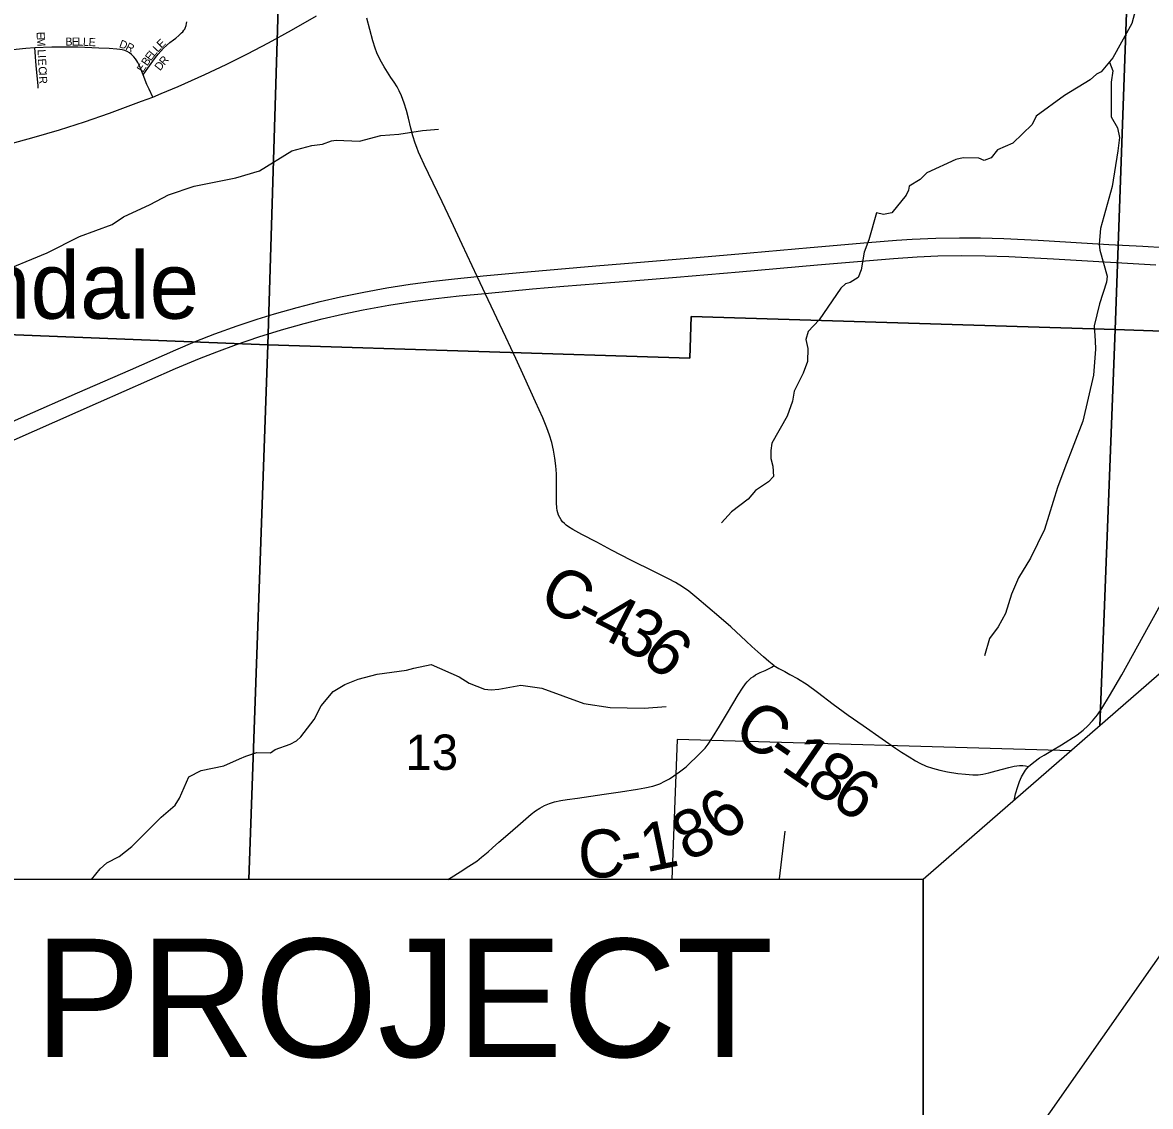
# Model space of a CAD drawing. Extents: x 0 to 34, y 0 to 22.
# Drawn here: x 25.311 to 26.645, y 15.353 to 16.636 of the extents above; entities that cross this region are included whole.
import ezdxf

# ---------------------------------------------------------------- set-up
doc = ezdxf.new("R2010")
doc.units = 0
for name, color, linetype in [('GM_X_County_Road', 7, 'Continuous'), ('GM_X_County_Road_Text', 7, 'Continuous'), ('GM_X_Interstate_Route', 7, 'Continuous'), ('GM_X_Minor_River', 7, 'Continuous'), ('GM_X_Section', 7, 'Continuous'), ('GM_X_Section_Text', 7, 'Continuous'), ('GM_X_Township_Subdivision', 7, 'Continuous'), ('GM_X_Township_Subdivision_Text', 7, 'Continuous'), ('GM_X_Unincorporated_Text', 7, 'Continuous'), ('GM_X_US_Route', 7, 'Continuous'), ('SH_Text', 7, 'Continuous')]:
    doc.layers.add(name, color=color, linetype=linetype)

msp = doc.modelspace()

# ---------------------------------------------------------------- linework, layer by layer
at = {"layer": 'GM_X_County_Road'}
for points in [[(25.7815, 16.4769), (25.7793, 16.4821), (25.7772, 16.4876), (25.7753, 16.4927), (25.7726, 16.5015), (25.7703, 16.5104), (25.7675, 16.5224), (25.7652, 16.5314), (25.7625, 16.5403), (25.7592, 16.549), (25.7566, 16.5547), (25.7539, 16.5595), (25.7504, 16.5648), (25.7467, 16.5704), (25.7385, 16.5833), (25.734, 16.5913), (25.7301, 16.5996), (25.728, 16.6053), (25.7253, 16.614), (25.7183, 16.6408)], [(26.1996, 15.8745), (26.1937, 15.8792), (26.1876, 15.8847), (26.1807, 15.8908), (26.1737, 15.897), (26.1669, 15.9033), (26.1487, 15.9201), (26.1347, 15.9325), (26.1087, 15.9546), (26.099, 15.9624), (26.0917, 15.9677), (26.0833, 15.9727), (26.0751, 15.9772), (26.0584, 15.9855), (26.0305, 15.9992), (26.0078, 16.0109), (25.9902, 16.0203), (25.9727, 16.0295), (25.9618, 16.0354), (25.9566, 16.0387), (25.9542, 16.0405), (25.9519, 16.0425), (25.9498, 16.0447), (25.948, 16.047), (25.9464, 16.0496), (25.9451, 16.0523), (25.9441, 16.0551), (25.9434, 16.0581), (25.9429, 16.0611), (25.9425, 16.0672), (25.9427, 16.0858), (25.9424, 16.1014), (25.9417, 16.1107), (25.9407, 16.12), (25.9391, 16.1292), (25.937, 16.1383), (25.9342, 16.1473), (25.9311, 16.156), (25.9263, 16.1675), (25.9177, 16.1864), (25.9046, 16.2153), (25.8945, 16.238), (25.8826, 16.2632), (25.8581, 16.3149), (25.8494, 16.3334), (25.8487, 16.3349), (25.8309, 16.3728), (25.8178, 16.4009), (25.8072, 16.4233), (25.7911, 16.4568), (25.7858, 16.4677), (25.7815, 16.4769)], [(26.5012, 15.7548), (26.5075, 15.7601), (26.5143, 15.765), (26.5196, 15.7685), (26.5293, 15.7744), (26.54, 15.7805), (26.5585, 15.7924), (26.5658, 15.798), (26.5713, 15.8031), (26.5767, 15.8088), (26.5826, 15.816), (26.588, 15.8235), (26.5969, 15.8385), (26.6116, 15.8635), (26.643, 15.9206), (26.6613, 15.9533)], [(25.8141, 15.621), (25.818, 15.6236), (25.8285, 15.6302), (25.839, 15.6369), (25.8482, 15.643), (25.854, 15.6477), (25.8617, 15.6538), (25.8669, 15.6586), (25.8744, 15.6654), (25.8851, 15.6746), (25.8967, 15.6848), (25.9126, 15.6985), (25.9176, 15.7023), (25.9229, 15.7057), (25.9284, 15.7087), (25.9342, 15.7112), (25.9401, 15.7132), (25.9476, 15.7147), (25.9552, 15.7158), (25.9673, 15.7174), (25.9988, 15.7223), (26.0185, 15.7249), (26.0385, 15.7279), (26.0471, 15.7295), (26.0565, 15.7317), (26.0649, 15.7346), (26.0709, 15.7376), (26.0763, 15.7405), (26.0815, 15.7439), (26.0883, 15.7487), (26.0961, 15.7546), (26.1012, 15.7595), (26.1076, 15.7657), (26.1142, 15.7721), (26.1184, 15.7767), (26.1222, 15.7815), (26.1273, 15.7892), (26.1353, 15.8025), (26.1448, 15.8185), (26.1576, 15.8399), (26.1626, 15.8478), (26.1663, 15.8529), (26.1683, 15.8553), (26.1705, 15.8575), (26.1729, 15.8597), (26.1755, 15.8616), (26.1781, 15.8633), (26.1837, 15.8662), (26.1894, 15.8687), (26.1943, 15.871), (26.1974, 15.8725), (26.1996, 15.8745)], [(26.1996, 15.8745), (26.2055, 15.8708), (26.2127, 15.8672), (26.2188, 15.8639), (26.2276, 15.8591), (26.2391, 15.8518), (26.2515, 15.8428), (26.2701, 15.8286), (26.2877, 15.8158), (26.3055, 15.8033), (26.328, 15.7877), (26.3438, 15.7767), (26.3509, 15.7719), (26.3597, 15.7662), (26.3673, 15.7615), (26.3727, 15.7587), (26.3802, 15.7552), (26.3874, 15.753), (26.396, 15.7507), (26.4051, 15.7487), (26.4173, 15.7467), (26.4266, 15.7457), (26.4354, 15.7451), (26.4415, 15.7452), (26.4472, 15.7459), (26.4541, 15.7473), (26.463, 15.7496), (26.478, 15.7539), (26.4841, 15.7553), (26.4904, 15.7563), (26.4943, 15.7563), (26.4975, 15.7559), (26.5012, 15.7548)], [(26.484, 15.7145), (26.4858, 15.7226), (26.4884, 15.7314), (26.4905, 15.7372), (26.493, 15.7427), (26.4951, 15.7468), (26.4974, 15.7504), (26.5012, 15.7548)]]:
    msp.add_lwpolyline(points, dxfattribs=at)
at = {"layer": 'GM_X_Interstate_Route'}
for points in [[(25.2706, 16.1507), (25.3132, 16.1695), (25.3758, 16.1971), (25.4383, 16.2246), (25.4923, 16.2483), (25.5152, 16.2579), (25.5384, 16.267), (25.5646, 16.2764), (25.5882, 16.2843), (25.6089, 16.2907), (25.6358, 16.2983), (25.6629, 16.3053), (25.6871, 16.311), (25.7144, 16.3166), (25.7419, 16.3215), (25.7695, 16.3257), (25.7972, 16.3293), (25.8219, 16.3321), (25.8487, 16.3349), (25.8559, 16.3357), (25.8992, 16.3396), (25.989, 16.3474), (26.023, 16.3503), (26.1221, 16.3588), (26.1716, 16.3631), (26.2428, 16.3693), (26.3109, 16.3752), (26.3449, 16.3779), (26.3635, 16.379), (26.3915, 16.3803), (26.4194, 16.3809), (26.4442, 16.3808), (26.4721, 16.38), (26.5125, 16.378), (26.5962, 16.3729), (26.6365, 16.3707), (26.7389, 16.3647)], [(25.2729, 16.1292), (25.4007, 16.1858), (25.4917, 16.226), (25.5203, 16.238), (25.5406, 16.2459), (25.5639, 16.2545), (25.5905, 16.2634), (25.6172, 16.2717), (25.6441, 16.2793), (25.6652, 16.2848), (25.6894, 16.2905), (25.7137, 16.2955), (25.7443, 16.3012), (25.772, 16.3055), (25.7997, 16.3091), (25.8275, 16.312), (25.8581, 16.3149), (25.9141, 16.3203), (25.9512, 16.3234), (26.0318, 16.3297), (26.0844, 16.3341), (26.1586, 16.3406), (26.2515, 16.3489), (26.3413, 16.3564), (26.3692, 16.3583), (26.394, 16.3594), (26.422, 16.3599), (26.45, 16.3596), (26.478, 16.3586), (26.5307, 16.3558), (26.6517, 16.3488)]]:
    msp.add_lwpolyline(points, dxfattribs=at)
at = {"layer": 'GM_X_Minor_River'}
for points in [[(26.6278, 16.6507), (26.6234, 16.6343), (26.601, 16.5936), (26.5871, 16.5772), (26.5814, 16.5745), (26.5739, 16.5677), (26.5437, 16.5493), (26.5101, 16.5248), (26.5053, 16.5149), (26.4827, 16.4927), (26.4646, 16.4847), (26.4571, 16.4755), (26.4487, 16.4724), (26.4423, 16.475), (26.4237, 16.4753), (26.415, 16.4733), (26.3807, 16.4576), (26.3728, 16.4496), (26.3599, 16.4419), (26.3592, 16.437), (26.3562, 16.4313), (26.3393, 16.4103), (26.3295, 16.4083), (26.3211, 16.4102), (26.3123, 16.3783), (26.3067, 16.3638), (26.303, 16.3429), (26.2997, 16.3338), (26.2902, 16.3277), (26.2846, 16.3261), (26.2789, 16.3212), (26.2534, 16.2838), (26.2403, 16.2697), (26.2377, 16.2602), (26.24, 16.2496)], [(26.5969, 16.5888), (26.6007, 16.5784), (26.5989, 16.5648), (26.5991, 16.5238), (26.6064, 16.511), (26.6088, 16.4996), (26.607, 16.4837), (26.6001, 16.4415), (26.5864, 16.3917), (26.5846, 16.3731), (26.5854, 16.3663), (26.594, 16.3353), (26.5932, 16.3284), (26.5851, 16.3026), (26.5788, 16.2764), (26.5801, 16.2586), (26.5805, 16.2491), (26.5781, 16.2183), (26.5652, 16.1636), (26.544, 16.1085), (26.5354, 16.0853), (26.5202, 16.0355), (26.5034, 16.0017), (26.4891, 15.9781), (26.4809, 15.959), (26.4739, 15.9362), (26.4653, 15.9203), (26.4548, 15.9065), (26.4492, 15.886)], [(25.2785, 16.3376), (25.3397, 16.363), (25.3782, 16.3823), (25.4167, 16.3965), (25.4303, 16.4057), (25.4617, 16.42), (25.4835, 16.4318), (25.5138, 16.4419), (25.5633, 16.4517), (25.5913, 16.4602), (25.6294, 16.4836), (25.6532, 16.4902), (25.6657, 16.4914), (25.6763, 16.4956), (25.682, 16.4964), (25.7096, 16.4951), (25.7346, 16.5017), (25.7562, 16.5034), (25.7842, 16.5077), (25.8031, 16.5093)], [(26.24, 16.2496), (26.2397, 16.2344), (26.2345, 16.2207), (26.2237, 16.1994), (26.2219, 16.1873), (26.2155, 16.1698), (26.1972, 16.1378), (26.1961, 16.1291), (26.1962, 16.1196), (26.1985, 16.1105), (26.1993, 16.0984), (26.1933, 16.0919), (26.1779, 16.0816), (26.1692, 16.0713), (26.1496, 16.0563), (26.138, 16.0434)], [(25.3922, 15.621), (25.4025, 15.6336), (25.4104, 15.6409), (25.4251, 15.6482), (25.4402, 15.6604), (25.4748, 15.6948), (25.4914, 15.7093), (25.4966, 15.7173), (25.5074, 15.7428), (25.5222, 15.7501), (25.549, 15.7556), (25.5675, 15.764), (25.5751, 15.7671), (25.5879, 15.7714), (25.6042, 15.7711), (25.6095, 15.7749), (25.6276, 15.7815), (25.6348, 15.7853), (25.6401, 15.7899), (25.6558, 15.8105), (25.6641, 15.8268), (25.6784, 15.8436), (25.6923, 15.8521), (25.7078, 15.8582), (25.7305, 15.8644), (25.7649, 15.8688), (25.7736, 15.8715), (25.7944, 15.8755), (25.8275, 15.8612), (25.8393, 15.8534), (25.8575, 15.8466), (25.8651, 15.8456), (25.8742, 15.8464), (25.9003, 15.8511), (25.9253, 15.8478)], [(25.9253, 15.8478), (25.975, 15.8296), (26.0061, 15.8248), (26.0463, 15.8239), (26.0724, 15.826)], [(26.2063, 15.621), (26.2063, 15.622), (26.2131, 15.6782)]]:
    msp.add_lwpolyline(points, dxfattribs=at)
at = {"layer": 'GM_X_Section'}
for points in [[(24.6507, 17.2941), (25.6316, 17.2576), (25.601, 16.254), (24.6148, 16.293)], [(26.6394, 17.2767), (26.6035, 16.2723), (26.1021, 16.2877), (26.1002, 16.2381), (25.601, 16.254), (25.6316, 17.2576), (26.1357, 17.2414), (26.1369, 17.2827)]]:
    msp.add_lwpolyline(points, close=True, dxfattribs=at)
for points in [[(27.1036, 16.2543), (26.6035, 16.2723), (26.6394, 17.2767), (27.6271, 17.2407), (27.6008, 16.4208)], [(24.6207, 15.2914), (24.5727, 15.2931), (24.6148, 16.293), (25.601, 16.254), (25.5786, 15.621)], [(25.5786, 15.621), (25.601, 16.254), (26.1002, 16.2381), (26.1021, 16.2877), (26.6035, 16.2723), (26.5857, 15.8032)], [(26.5857, 15.8032), (26.6035, 16.2723), (27.1036, 16.2543)], [(26.5518, 15.7736), (26.0854, 15.7867), (26.0789, 15.621)]]:
    msp.add_lwpolyline(points, dxfattribs=at)
at = {"layer": 'GM_X_Township_Subdivision'}
for points in [[(25.4535, 16.5738), (25.4592, 16.5814), (25.465, 16.5898), (25.4681, 16.5943), (25.4712, 16.5982), (25.4744, 16.6018), (25.4777, 16.6054), (25.481, 16.6084), (25.485, 16.6118), (25.4892, 16.6151), (25.492, 16.6172), (25.4956, 16.6202), (25.499, 16.6232), (25.5005, 16.6247), (25.5018, 16.6264), (25.5026, 16.6276), (25.5033, 16.6291), (25.5043, 16.6321), (25.5048, 16.6343), (25.5051, 16.6363)], [(25.3254, 16.6055), (25.3145, 16.605), (25.2837, 16.6018), (25.2713, 16.6011), (25.2684, 16.6012), (25.2651, 16.6016), (25.2622, 16.6022), (25.2592, 16.6032), (25.256, 16.6047), (25.2538, 16.6062), (25.2527, 16.607), (25.2514, 16.6082), (25.2495, 16.6106)], [(25.4535, 16.5738), (25.4512, 16.5797), (25.4491, 16.5844), (25.4473, 16.5881), (25.4458, 16.5904), (25.4443, 16.5928), (25.4426, 16.5949), (25.4398, 16.5978), (25.4373, 16.5996), (25.4346, 16.6011), (25.4319, 16.6023), (25.4288, 16.6031), (25.4257, 16.6038), (25.4222, 16.6042), (25.4134, 16.6047), (25.4011, 16.6053), (25.3763, 16.6066), (25.3454, 16.6065), (25.3254, 16.6055)], [(25.3294, 16.5577), (25.3293, 16.5607), (25.327, 16.5848), (25.3254, 16.6055)], [(25.4648, 16.5474), (25.4606, 16.5568), (25.458, 16.5624), (25.4535, 16.5738)]]:
    msp.add_lwpolyline(points, dxfattribs=at)
at = {"layer": 'GM_X_US_Route'}
msp.add_lwpolyline([(25.2945, 16.4917), (25.3246, 16.4998), (25.3545, 16.5086), (25.3842, 16.518), (25.4137, 16.5282), (25.4517, 16.5423), (25.4648, 16.5474), (25.4749, 16.5514), (25.495, 16.5599), (25.5263, 16.5739), (25.5517, 16.5859), (25.5768, 16.5984), (25.6016, 16.6114), (25.6289, 16.6265), (25.6585, 16.6437)], dxfattribs=at)
at = {"layer": 'SH_Text'}
for points in [[(27.2563, 16.3872), (26.3766, 15.621), (26.3766, 15.131)], [(24.6207, 15.131), (26.3766, 15.131), (26.3766, 15.621), (24.6207, 15.621)]]:
    msp.add_lwpolyline(points, close=True, dxfattribs=at)

# ---------------------------------------------------------------- texts
at = {"layer": 'GM_X_County_Road_Text'}
for s, rotation, p in [('C', 332.9183, (25.9189, 15.9463)), ('4', 332.788, (25.9812, 15.9144)), ('-', 332.8904, (25.9605, 15.925)), ('3', 330.6598, (26.0119, 15.8987)), ('6', 320.0772, (26.0401, 15.8831)), ('C', 325.3443, (26.1488, 15.7915)), ('-', 325.3481, (26.1872, 15.7649)), ('1', 325.3946, (26.2064, 15.7516)), ('8', 325.4878, (26.2353, 15.7317)), ('6', 325.8734, (26.2645, 15.7116)), ('6', 37.6569, (26.139, 15.6637)), ('8', 26.3951, (26.0974, 15.6417)), ('1', 11.7883, (26.0482, 15.6294)), ('C', 3.7575, (25.9699, 15.6217)), ('-', 8.4901, (26.0216, 15.6253))]:
    msp.add_text(s, height=0.0568, rotation=rotation, dxfattribs=at).set_placement(p)
at = {"layer": 'GM_X_Section_Text'}
msp.add_text('13', height=0.04186, rotation=0, dxfattribs=at).set_placement((25.7639, 15.7509))
at = {"layer": 'GM_X_Township_Subdivision_Text'}
for s, rotation, p in [('E', 273.1707, (25.3273, 16.6243)), ('M', 273.1344, (25.3277, 16.6176)), ('B', 359.9514, (25.3614, 16.6083)), ('E', 359.6996, (25.3689, 16.6083)), ('L', 358.333, (25.3755, 16.6083)), ('L', 357.7596, (25.3821, 16.6081)), ('E', 357.705, (25.3888, 16.6078)), ('E', 45.1159, (25.4752, 16.6045)), ('I', 273.1639, (25.3283, 16.6076)), ('L', 273.1707, (25.3285, 16.6035)), ('D', 339.8226, (25.4243, 16.6066)), ('R', 332.9789, (25.4319, 16.6039)), ('L', 45.734, (25.4706, 16.5997)), ('I', 273.1483, (25.3289, 16.5968)), ('E', 273.1162, (25.3291, 16.5926)), ('B', 55.0836, (25.4582, 16.5835)), ('E', 52.5347, (25.4624, 16.5895)), ('L', 50.0091, (25.4664, 16.5948)), ('R', 49.5041, (25.4786, 16.5843)), ('C', 273.1583, (25.3296, 16.5835)), ('E', 57.6587, (25.4533, 16.5759)), ('D', 51.7703, (25.4735, 16.5778)), ('I', 273.1483, (25.33, 16.576)), ('R', 273.1526, (25.3302, 16.5718))]:
    msp.add_text(s, height=0.00947, rotation=rotation, dxfattribs=at).set_placement(p)
at = {"layer": 'GM_X_Unincorporated_Text'}
msp.add_text('Sundale', height=0.07898, rotation=0, dxfattribs=at).set_placement((25.1322, 16.285))
at = {"layer": 'SH_Text'}
msp.add_text('BEGIN PROJECT', height=0.14, dxfattribs=at).set_placement((24.6907, 15.411))

doc.saveas('drawing.dxf')
